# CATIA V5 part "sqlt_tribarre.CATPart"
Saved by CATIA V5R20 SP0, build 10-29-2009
Part number: sqlt_tribarre
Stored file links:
  D:\ecole\thinkmotion\sqlt_tribarre.CATPart
  D:\ecole\thinkmotion\sqlt_eolienne.CATProduct
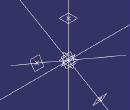
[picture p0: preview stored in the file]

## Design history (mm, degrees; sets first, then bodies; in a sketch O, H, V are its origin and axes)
External parameters (linked from other documents)
  External.longeur_barre = 1000 mm
  `External.diamètre_trou` = 40 mm
  External.rayon_bati = 50 mm
  `External.rayon_pivot-rayon_bati` = 30 mm
  External.profondeur_trou = 25 mm
Body1 (main body)
  Plane1: type Offset, RefPlane xy-plane, Offset 0
  Point1: (0, 0, 0)
  Plane2: type Offset, RefPlane Plane1, Offset 1085 {= External.rayon_bati +`External.rayon_pivot-rayon_bati` +30mm+External.longeur_barre -External.profondeur_trou}
  Line1: type Normal, LineFirstUpto Plane2, RefPoint Point1, RefSkin Plane1, Start 0, End 20
  Line2: type PtDir, RefPoint Point1, Direction yz-plane, Start 0, End 20
  Plane3: type Angle, RefPlane Plane1, Direction Line2, Angle 120
  Line3: type Normal, RefPoint Point1, RefSkin Plane3, Start 0, End 20
  Plane4: type Angle, RefPlane Plane3, Direction Line2, Angle 120
  Line4: type Normal, RefPoint Point1, RefSkin Plane4, Start 0, End 20
  Plane5: type Offset, RefPlane Plane3, Offset 1085 {= External.rayon_bati +`External.rayon_pivot-rayon_bati` +30mm+External.longeur_barre -External.profondeur_trou}
  Plane6: type Offset, RefPlane Plane4, Offset 1085 {= External.rayon_bati +`External.rayon_pivot-rayon_bati` +30mm+External.longeur_barre -External.profondeur_trou}
  Point2: type OnPlane, Support Plane2, H 0, V 0, Direction (1, 0, 0)
  Point3: type OnPlane, Support Plane5, H 0, V 0, Direction (1, 0, 0)
  Point4: type OnPlane, Support Plane6, H 0, V 0, Direction (-1, 0, 0)
  Point5: type OnPlane, Support Plane5, H 0, V 20 {= `External.diamètre_trou` /2}, Direction (1, 0, 0)
  Point6: type OnPlane, Support Plane2, H 0, V 20 {= `External.diamètre_trou` /2}, Direction (1, 0, 0)
  Point7: type OnPlane, Support Plane6, H 0, V 20 {= `External.diamètre_trou` /2}, Direction (-1, 0, 0)
  Plane7: type Offset, RefPlane yz-plane, Offset 0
